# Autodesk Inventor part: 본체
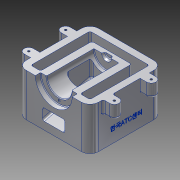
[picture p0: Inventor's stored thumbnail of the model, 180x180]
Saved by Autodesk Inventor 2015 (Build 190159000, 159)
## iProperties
Created: 2022-03
Part Number: 본체
Material: 알루미늄 6061
Document SubType Name: Modeling
Designer: pc-04
Density: 2.7 g/cm^3
Appearance: 알루미늄 - 평지
Mass: 1024.73 g
Surface Area: 849.872 cm^2
Volume: 379.531 cm^3
Author: pc-04
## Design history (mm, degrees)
sketch "스케치1"
  geometry: L1 (-42, 55)-(42, 55); L2 (55, 42)-(55, -42); L3 (42, -55)-(-42, -55); L4 (-55, -42)-(-55, 42); L5 (-55, 55)-(55, -55); L6 (55, 55)-(-55, -55); A1 r 13 centre (-42, 42) between (-42, 55) and (-55, 42); A2 r 13 centre (42, 42) between (55, 42) and (42, 55); A3 r 13 centre (-42, -42) between (-55, -42) and (-42, -55); A4 r 13 centre (42, -42) between (42, -55) and (55, -42); 1 further point
  constraints: 12 end point, 8 point on circle, 8 point on line, 8 tangent, 4 centre point, 3 equal radius, 2 midpoint, 2 parallel, 1 horizontal, 1 perpendicular
  dimensions: "d0" = 110 distance of L5.start L6.start; "d1" = 110 distance of L6.end L5.start; "d2" = 13 radius of A1
extrude "돌출1" new body sketch "스케치1" distance "d3" = 65; taper "d4" = 0 deg
sketch "스케치2"
  geometry: L1 (-42, -55)-(42, -55) reference; L2 (42, 55)-(-42, 55) reference; L3 (42, -28)-(-42, -28); L4 (-42, 28)-(42, 28); L5 (-65, 28)-(65, 28); L6 (-65, -28)-(65, -28); L7 (55, -42)-(55, 42) reference; L8 (55, 35)-(55, 21); L9 (-55, 42)-(-55, -42) reference; L10 (-55, 35)-(-55, 21); L11 (-55, -21)-(-55, -35); L12 (55, -21)-(55, -35); L13 (-65, -35)-(-55, -35); L14 (55, -35)-(65, -35); L15 (-65, -21)-(-55, -21); L16 (55, -21)-(65, -21); L17 (-65, 35)-(-55, 35); L18 (55, 35)-(65, 35); L19 (-65, 21)-(-55, 21); L20 (55, 21)-(65, 21); A1 r 7 centre (-65, 28) between (-65, 35) and (-65, 21); A2 r 7 centre (-65, -28) between (-65, -21) and (-65, -35); A3 r 7 centre (65, 28) between (65, 21) and (65, 35); A4 r 7 centre (65, -28) between (65, -35) and (65, -21); 7 further points
  constraints: 32 end point, 8 point on circle, 8 point on line, 8 tangent, 6 coincident, 6 horizontal, 6 midpoint, 4 centre point, 2 parallel, 2 vertical alignment
  dimensions: "d6" = 83 distance between parallel lines of L2 L3; "d7" = 83 distance between parallel lines of L1 L4; "d8" = 130 distance of L5.start L5.end; "d9" = 130 distance of L6.start L6.end; "d10" = 14 diameter of A1; "d11" = 14 diameter of A2; "d12" = 14 diameter of A3; "d13" = 14 diameter of A4; "d14" = 90 deg angle of L18 L7; "d15" = 90 deg angle of L16 L7; "d16" = 34 distance between parallel lines of L20 L2; "d17" = 90 distance between parallel lines of L14 L2; "d18" = 13 distance from line of L4.end L7; "d19" = 13 distance from line of L3.start L7; "d20" = 55 distance from line of point (0, 28) L7; "d21" = 55 distance from line of point (0, -28) L7
extrude "돌출2" join sketch "스케치2" distance "d22" = 20; taper "d23" = 0 deg
sketch "스케치3"
  geometry: L1 (42, 55)-(-42, 55) reference; L2 (-42, -55)-(42, -55) reference; L3 (-55, 21)-(-55, -21) reference; L4 (55, -21)-(55, 21) reference; L5 (42, 45)-(-42, 45); L6 (45, -42)-(45, 42); L7 (-45, 42)-(-45, -42); L8 (27, 33)-(-27, 33); L9 (30, -42)-(30, 30); L10 (-30, 30)-(-30, -42); L11 (-42, -45)-(-33, -45); L12 (33, -45)-(42, -45); A1 r 3 centre (-42, 42) between (-42, 45) and (-45, 42); A2 r 3 centre (42, 42) between (45, 42) and (42, 45); A3 r 3 centre (-27, 30) between (-27, 33) and (-30, 30); A4 r 3 centre (27, 30) between (30, 30) and (27, 33); A5 r 3 centre (-42, -42) between (-45, -42) and (-42, -45); A6 r 3 centre (-33, -42) between (-33, -45) and (-30, -42); A7 r 3 centre (33, -42) between (30, -42) and (33, -45); A8 r 3 centre (42, -42) between (42, -45) and (45, -42); 1 further point
  constraints: 16 end point, 16 point on circle, 16 tangent, 8 centre point, 8 parallel, 7 equal radius
  dimensions: "d24" = 10 distance between parallel lines of L1 L5; "d26" = 10 distance between parallel lines of L4 L6; "d27" = 10 distance between parallel lines of L3 L7; "d28" = 22 distance between parallel lines of L1 L8; "d29" = 25 distance between parallel lines of L4 L9; "d30" = 25 distance between parallel lines of L3 L10; "d31" = 100 distance between parallel lines of L1 L12; "d32" = 100 distance between parallel lines of L1 L11; "d33" = 3 radius of A1
extrude "돌출3" cut sketch "스케치3" stored distance "d34" = 20; taper "d35" = 0 deg
sketch "스케치4"
  geometry: A1 r 7 centre (-65, 28) between (-65, 35) and (-65, 21) reference; A2 r 7 centre (-65, -28) between (-65, -21) and (-65, -35) reference; A3 r 7 centre (65, 28) between (65, 21) and (65, 35) reference; A4 r 7 centre (65, -28) between (65, -35) and (65, -21) reference; 5 further points
  constraints: 4 coincident
hole "구멍1" sketch "스케치4" at (-65, 28), (-65, -28), (65, 28), (65, -28) diameter "d36" = 3.242; stored, may be unused: countersink angle "d40" = 90 deg, drill point angle "d42" = 118 deg; dims "d37" = 9, "d38" = 4, "d39" = 2, "d41" = 11
sketch "스케치5"
  geometry: L1 (-42, 65)-(30, 65) reference; L2 (30, 0)-(-42, 0) reference; L3 (-55, 0)-(-55, 65) reference; L4 (55, 0)-(55, 65) reference; L5 (55, 65)-(-55, 65); L6 (-55, 65)-(-47, 65); L7 (-47, 65)-(-47, 37); L8 (-47, 37)-(-55, 37); L9 (-55, 37)-(-55, 65); L10 (-47, 65)-(25, 65); L11 (25, 65)-(25, 46); L12 (25, 46)-(-47, 46); L13 (-47, 46)-(-47, 65); 1 further point
  constraints: 18 end point, 4 parallel, 3 horizontal, 2 perpendicular
  dimensions: "d43" = 8 distance of L7.end L8.end; "d44" = 72 distance of L11.end L12.end; "d45" = 56 diameter of L8 L5; "d47" = 38 diameter of L12 L5
revolve "회전1" sketch "스케치5" stored, may be unused: angle "d48" = 90 deg
sketch "스케치6"
  geometry: L1 (-19, 0)-(19, 0) reference; C1 r 7.5 at (0, 0); 1 further point
  constraints: 1 centre point, 1 midpoint
  dimensions: "d49" = 15 diameter of C1
extrude "돌출4" cut sketch "스케치6" distance "d50" = 4; taper "d51" = -30 deg
sketch "스케치7" dims "d52" = 46
  geometry: L1 (-5.191, 0)-(5.191, 0) reference; 3 further points
  constraints: 1 vertical alignment, 2 other
  dimensions: "d53" = 23 distance from line of L1 point (0, -23); "d54" = 0 distance from line of point (0, 0) L1; "d55" = 5.1906 distance of L1.end point (0, 0)
hole "구멍2" sketch "스케치7" at (0, -23) diameter "d56" = 3.242; stored, may be unused: countersink angle "d60" = 90 deg, drill point angle "d62" = 118 deg; dims "d57" = 9, "d58" = 4, "d59" = 2, "d61" = 11
sketch "스케치8"
  geometry: L1 (55, 0)-(55, 65) reference; L2 (-55, 0)-(-55, 65) reference; L3 (30, 0)-(-42, 0) reference; L4 (25, 65)-(-47, 65) reference; L5 (33, 30)-(-42.776, 9.696); L6 (-45, 0)-(-45, 65); L7 (-45, 6.798)-(-45, 0); L8 (-45, 0)-(33, 0); L9 (33, 0)-(33, 30); L10 (16.776, 30.829)-(-55, 11.597); L11 (-21.224, 38.247)-(-55, 29.197); L12 (-19, 41.145)-(-19, 65); L13 (19, 33.727)-(19, 65); L14 (19, 65)-(-19, 65); L15 (-55, 29.197)-(-55, 11.597); A1 r 3 centre (-42, 6.798) between (-42.776, 9.696) and (-45, 6.798); A2 r 3 centre (16, 33.727) between (16.776, 30.829) and (19, 33.727); A3 r 3 centre (-22, 41.145) between (-21.224, 38.247) and (-19, 41.145); 2 further points
  constraints: 22 end point, 6 parallel, 6 point on circle, 6 tangent, 5 point on line, 3 centre point, 2 collinear, 2 equal radius, 2 perpendicular
  dimensions: "d71" = 15 deg angle of L3 L5; "d72" = 28.11338 distance from line of L1.end L5; "d73" = 65 distance from line of L6.end L3; "d76" = 5 distance between parallel lines of L5 L10; "d77" = 17 distance between parallel lines of L10 L11; "d78" = 36 distance between parallel lines of L2 L12; "d79" = 38 distance between parallel lines of L12 L13; "d80" = 3 radius of A1; "d81" = 0 distance between parallel lines of L4 L14
extrude "돌출5" cut sketch "스케치8" stored distance "d74" = 60; taper "d75" = 0 deg
extrude "돌출6" cut sketch "스케치8" stored distance "d82" = 34; taper "d83" = 0 deg
fillet "모깎기1" dims "d84" = 3
chamfer "모따기1" distance "d85" = 1; stored, may be unused: second distance "d86" = 2, angle "d87" = 45 deg
fillet "모깎기2" dims "d88" = 3
fillet "모깎기3" dims "d89" = 3
sketch "스케치9"
  geometry: L1 (0, -13)-(-65, -13) reference; 2 further points
  constraints: 1 other
  dimensions: "d90" = 55 distance from line of L1 point (-20, 42); "d91" = 20 distance of point (0, 42) point (-20, 42)
feature "엠보싱1" sketch "스케치9" dims "d0" = 110, "d1" = 110, "d2" = 13, "d7" = 83, "d8" = 130, "d10" = 14, "d12" = 14, "d14" = 90 deg, "d16" = 34, "d18" = 13, "d20" = 55, "d92" = 0.5, "d93" = 0
node "솔리드1"
